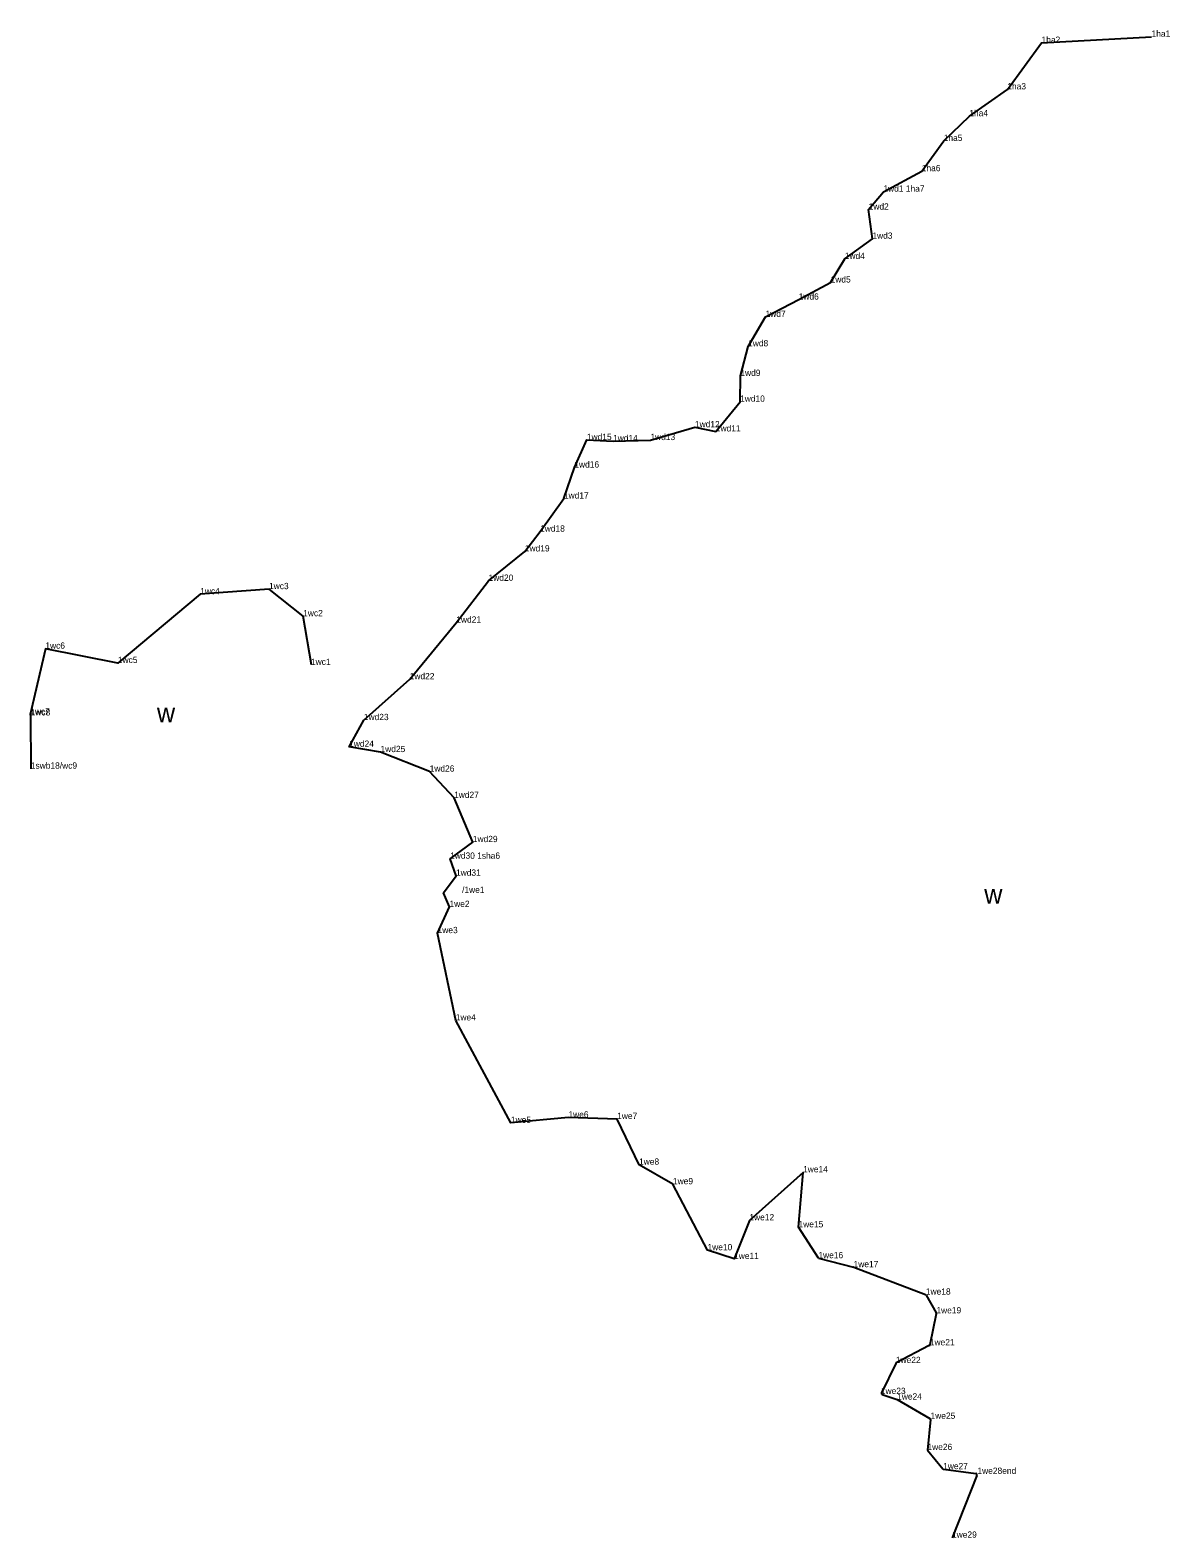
# Model space of a CAD drawing. Extents: x 2072529 to 2267990, y 436423 to 470008.
# Drawn here: x 2075739 to 2076646, y 466464 to 467665 of the extents above; entities that cross this region are included whole.
import ezdxf

# ---------------------------------------------------------------- set-up
doc = ezdxf.new("R2010")
doc.units = 0
for name, color, linetype in [('Level 3', 7, 'Continuous'), ('Old_Level_52', 7, 'Continuous'), ('Prop SS Cut Line', 7, 'Continuous')]:
    doc.layers.add(name, color=color, linetype=linetype)

msp = doc.modelspace()

# ---------------------------------------------------------------- linework, layer by layer
at = {"layer": 'Level 3'}
for p, q in [((2076631.049, 467659.491), (2076631.049, 467659.491)), ((2076543.722, 467654.415), (2076543.722, 467654.415)), ((2076516.473, 467617.334), (2076516.473, 467617.334)), ((2076486.234, 467596.018), (2076486.234, 467596.018)), ((2076465.848, 467576.265), (2076465.848, 467576.265)), ((2076448.363, 467552.18), (2076448.363, 467552.18)), ((2076417.807, 467535.863), (2076417.807, 467535.863)), ((2076406.07, 467521.595), (2076406.07, 467521.595)), ((2076409.042, 467498.371), (2076409.042, 467498.371)), ((2076387.037, 467482.299), (2076387.037, 467482.299)), ((2076375.796, 467463.533), (2076375.796, 467463.533)), ((2076350.373, 467449.925), (2076350.373, 467449.925)), ((2076324.026, 467436.212), (2076324.026, 467436.212)), ((2076310.132, 467412.702), (2076310.132, 467412.702)), ((2076303.958, 467389.134), (2076303.958, 467389.134)), ((2076303.724, 467368.604), (2076303.724, 467368.604)), ((2076267.78, 467348.256), (2076267.78, 467348.256)), ((2076181.745, 467338.146), (2076181.745, 467338.146)), ((2076202.594, 467337.188), (2076202.594, 467337.188)), ((2076232.341, 467338.067), (2076232.341, 467338.067)), ((2076284.44, 467344.916), (2076284.44, 467344.916)), ((2076171.766, 467316.202), (2076171.766, 467316.202)), ((2076163.46, 467291.501), (2076163.46, 467291.501)), ((2076144.507, 467265.147), (2076144.507, 467265.147)), ((2076132.374, 467249.383), (2076132.374, 467249.383)), ((2076103.483, 467225.984), (2076103.483, 467225.984)), ((2075873.975, 467215.364), (2075873.975, 467215.364)), ((2075928.718, 467219.354), (2075928.718, 467219.354)), ((2075955.918, 467197.806), (2075955.918, 467197.806)), ((2076077.805, 467192.665), (2076077.805, 467192.665)), ((2075750.662, 467171.956), (2075750.662, 467171.956)), ((2075808.394, 467160.507), (2075808.394, 467160.507)), ((2075962.51, 467159.014), (2075962.51, 467159.014)), ((2076040.697, 467147.547), (2076040.697, 467147.547)), ((2075738.555, 467119.552), (2075738.555, 467119.552)), ((2075738.953, 467118.772), (2075738.953, 467118.772)), ((2076004.205, 467115.058), (2076004.205, 467115.058)), ((2075992.508, 467093.795), (2075992.508, 467093.795)), ((2076017.464, 467089.586), (2076017.464, 467089.586)), ((2075739.089, 467076.384), (2075739.089, 467076.384)), ((2076056.58, 467074.029), (2076056.58, 467074.029)), ((2076076.037, 467053.053), (2076076.037, 467053.053)), ((2076090.972, 467017.9), (2076090.972, 467017.9)), ((2076072.875, 467004.649), (2076072.875, 467004.649)), ((2076077.564, 466991.108), (2076077.564, 466991.108)), ((2076067.746, 466977.439), (2076067.746, 466977.439)), ((2076072.381, 466966.271), (2076072.381, 466966.271)), ((2076062.921, 466945.406), (2076062.921, 466945.406)), ((2076077.379, 466875.893), (2076077.379, 466875.893)), ((2076121.301, 466794.33), (2076121.301, 466794.33)), ((2076167.094, 466798.517), (2076167.094, 466798.517)), ((2076205.856, 466797.395), (2076205.856, 466797.395)), ((2076223.278, 466760.97), (2076223.278, 466760.97)), ((2076250.284, 466745.441), (2076250.284, 466745.441)), ((2076353.859, 466754.93), (2076353.859, 466754.93)), ((2076311.103, 466716.705), (2076311.103, 466716.705)), ((2076350.236, 466711.142), (2076350.236, 466711.142)), ((2076277.779, 466692.856), (2076277.779, 466692.856)), ((2076298.954, 466685.932), (2076298.954, 466685.932)), ((2076366.085, 466686.538), (2076366.085, 466686.538)), ((2076394.085, 466679.358), (2076394.085, 466679.358)), ((2076451.628, 466657.539), (2076451.628, 466657.539)), ((2076460.014, 466642.612), (2076460.014, 466642.612)), ((2076454.785, 466617.128), (2076454.785, 466617.128)), ((2076427.745, 466603.065), (2076427.745, 466603.065)), ((2076415.807, 466578.389), (2076415.807, 466578.389)), ((2076428.742, 466573.987), (2076428.742, 466573.987)), ((2076455.331, 466558.653), (2076455.331, 466558.653)), ((2076452.873, 466533.789), (2076452.873, 466533.789)), ((2076465.374, 466518.524), (2076465.374, 466518.524)), ((2076492.683, 466514.809), (2076492.683, 466514.809)), ((2076472.438, 466463.933), (2076472.438, 466463.933))]:
    msp.add_line(p, q, dxfattribs=at)
at = {"layer": 'Old_Level_52'}
for p, q in [((2076366.085, 466686.538), (2076394.031, 466679.372)), ((2076394.137, 466679.338), (2076451.289, 466657.668)), ((2076451.806, 466657.222), (2076459.831, 466642.937)), ((2076459.939, 466642.246), (2076454.881, 466617.594)), ((2076454.363, 466616.908), (2076428.039, 466603.218)), ((2076427.601, 466602.766), (2076416.299, 466579.407)), ((2076416.877, 466578.025), (2076428.649, 466574.019)), ((2076428.827, 466573.938), (2076454.772, 466558.975)), ((2076455.268, 466558.011), (2076452.873, 466533.789)), ((2076452.873, 466533.789), (2076465.125, 466518.828)), ((2076465.764, 466518.471), (2076491.416, 466514.981)), ((2076492.21, 466513.621), (2076472.438, 466463.933))]:
    msp.add_line(p, q, dxfattribs=at)
for points in [[(2076366.085, 466686.538), (2076350.236, 466711.142), (2076353.859, 466754.93), (2076311.103, 466716.705), (2076298.954, 466685.932), (2076277.779, 466692.856), (2076250.284, 466745.441), (2076223.278, 466760.97), (2076205.856, 466797.395), (2076167.094, 466798.517), (2076121.301, 466794.33), (2076077.379, 466875.893), (2076062.921, 466945.406), (2076072.381, 466966.271), (2076067.591, 466977.496), (2076077.564, 466991.108), (2076072.875, 467004.649), (2076090.972, 467017.9), (2076076.037, 467053.053), (2076056.58, 467074.029), (2076017.464, 467089.586), (2075992.508, 467093.795), (2076004.205, 467115.058), (2076040.697, 467147.547), (2076077.805, 467192.665), (2076103.483, 467225.984), (2076132.374, 467249.383), (2076144.507, 467265.147), (2076163.46, 467291.501), (2076171.766, 467316.202), (2076181.745, 467338.146), (2076202.594, 467337.188), (2076232.341, 467338.067), (2076267.78, 467348.256), (2076284.44, 467344.916), (2076303.724, 467368.604), (2076303.958, 467389.134), (2076310.132, 467412.702), (2076324.026, 467436.212), (2076350.373, 467449.925), (2076375.796, 467463.533), (2076387.037, 467482.299), (2076409.042, 467498.371), (2076406.07, 467521.595), (2076417.807, 467535.863), (2076448.363, 467552.18), (2076465.848, 467576.265), (2076486.234, 467596.018), (2076516.473, 467617.334), (2076543.722, 467654.415), (2076631.284, 467659.256)], [(2075962.51, 467159.014), (2075955.918, 467197.806), (2075928.718, 467219.354), (2075873.975, 467215.364), (2075808.394, 467160.507), (2075750.662, 467171.956), (2075738.555, 467119.552), (2075738.953, 467118.772), (2075739.089, 467076.384)]]:
    msp.add_lwpolyline(points, dxfattribs=at)
for centre, start, end in [((2076393.783, 466678.403), 69.234408, 75.617619), ((2076450.934, 466656.733), 29.327311, 69.234408), ((2076458.959, 466642.447), 348.404561, 29.327311), ((2076453.901, 466617.795), 297.4781, 348.404561), ((2076428.501, 466602.331), 117.4781, 154.182769), ((2076417.2, 466578.971), 154.182772, 251.205692), ((2076428.327, 466573.072), 60.02775, 71.205689), ((2076454.272, 466558.109), 354.354208, 60.02775), ((2076465.898, 466519.462), 219.31515, 262.253278), ((2076491.281, 466513.991), 338.300989, 82.253278)]:
    msp.add_arc(centre, 1, start, end, dxfattribs=at)

# ---------------------------------------------------------------- texts
for s, p in [('1ha2', (2076543.722, 467654.415)), ('1ha1', (2076631.284, 467659.256)), ('1ha3', (2076516.473, 467617.334)), ('1ha4', (2076486.234, 467596.018)), ('1ha5', (2076465.848, 467576.265)), ('1ha6', (2076448.363, 467552.18)), ('1wd1 1ha7', (2076417.807, 467535.863)), ('1wd2', (2076406.07, 467521.595)), ('1wd3', (2076409.042, 467498.371)), ('1wd4', (2076387.037, 467482.299)), ('1wd5', (2076375.796, 467463.533)), ('1wd6', (2076350.373, 467449.925)), ('1wd7', (2076324.026, 467436.212)), ('1wd8', (2076310.132, 467412.702)), ('1wd9', (2076303.958, 467389.134)), ('1wd10', (2076303.724, 467368.604)), ('1wd12', (2076267.78, 467348.256)), ('1wd11', (2076284.44, 467344.916)), ('1wd15', (2076181.745, 467338.146)), ('1wd14', (2076202.594, 467337.188)), ('1wd13', (2076232.341, 467338.067)), ('1wd16', (2076171.766, 467316.202)), ('1wd17', (2076163.46, 467291.501)), ('1wd18', (2076144.507, 467265.147)), ('1wd19', (2076132.374, 467249.383)), ('1wd20', (2076103.483, 467225.984)), ('1wc4', (2075873.975, 467215.364)), ('1wc3', (2075928.718, 467219.354)), ('1wc2', (2075955.918, 467197.806)), ('1wd21', (2076077.805, 467192.665)), ('1wc6', (2075750.662, 467171.956)), ('1wc5', (2075808.394, 467160.507)), ('1wc1', (2075962.103, 467159.014)), ('1wd22', (2076040.697, 467147.547)), ('1wc7', (2075738.555, 467119.552)), ('1wc8', (2075738.953, 467118.772)), ('1wd23', (2076004.205, 467115.058)), ('1wd24', (2075992.508, 467093.795)), ('1wd25', (2076017.464, 467089.586)), ('1swb18/wc9', (2075739.089, 467076.384)), ('1wd26', (2076056.58, 467074.029)), ('1wd27', (2076076.037, 467053.053)), ('1wd29', (2076090.972, 467017.9)), ('1wd30 1sha6', (2076072.875, 467004.649)), ('1wd31', (2076077.564, 466991.108)), ('/1we1', (2076082.402, 466977.442)), ('1we2', (2076072.381, 466966.271)), ('1we3', (2076062.921, 466945.406)), ('1we4', (2076077.379, 466875.893)), ('1we5', (2076121.301, 466794.33)), ('1we6', (2076167.094, 466798.517)), ('1we7', (2076205.856, 466797.395)), ('1we8', (2076223.278, 466760.97)), ('1we14', (2076353.859, 466754.93)), ('1we9', (2076250.284, 466745.441)), ('1we12', (2076311.103, 466716.705)), ('1we15', (2076350.236, 466711.142)), ('1we10', (2076277.779, 466692.856)), ('1we11', (2076298.954, 466685.932)), ('1we16', (2076366.085, 466686.538)), ('1we17', (2076394.085, 466679.358)), ('1we18', (2076451.628, 466657.539)), ('1we19', (2076460.014, 466642.612)), ('1we21', (2076454.785, 466617.128)), ('1we22', (2076427.745, 466603.065)), ('1we23', (2076415.807, 466578.389)), ('1we24', (2076428.742, 466573.987)), ('1we25', (2076455.331, 466558.653)), ('1we26', (2076452.873, 466533.789)), ('1we27', (2076465.374, 466518.524)), ('1we28end', (2076492.683, 466514.809)), ('1we29', (2076472.438, 466463.933))]:
    msp.add_text(s, height=5).set_placement(p)
at = {"layer": 'Prop SS Cut Line'}
for p in [(2075839.46, 467113.423), (2076498.065, 466968.993)]:
    msp.add_text('w', height=15, dxfattribs=at).set_placement(p)

doc.saveas('drawing.dxf')
